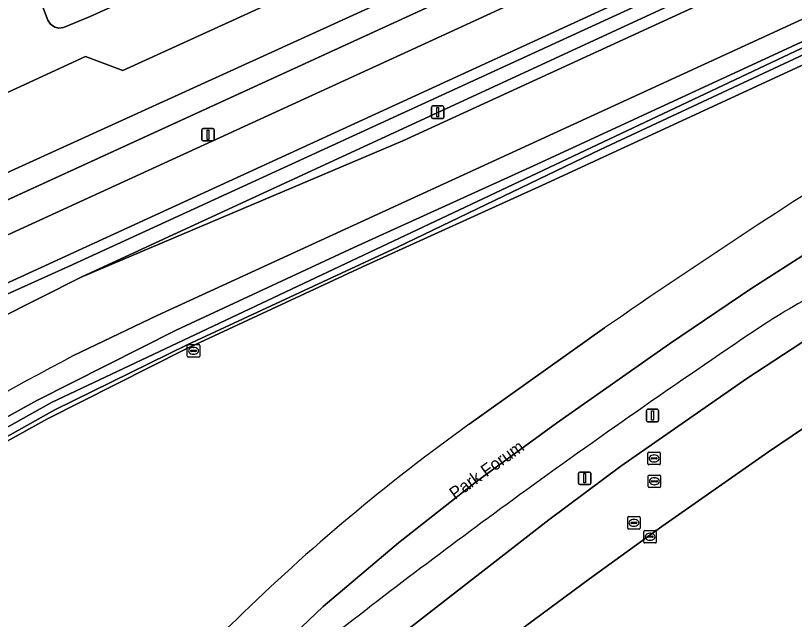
# Model space of a CAD drawing. Extents: x 154324 to 155744, y 382937 to 384188.
# Drawn here: x 155121.6 to 155184.3, y 383931.3 to 383979.9 of the extents above; entities that cross this region are included whole.
import ezdxf

# ---------------------------------------------------------------- set-up
doc = ezdxf.new("R2010")
doc.units = 0
for name, color, linetype in [('IMGEO_Berm_groen', 7, 'Continuous'), ('IMGEO_Brandkraan', 7, 'Continuous'), ('IMGEO_Fietspad_gesloten', 7, 'Continuous'), ('IMGEO_Groenvoorziening', 7, 'Continuous'), ('IMGEO_Hek', 7, 'Continuous'), ('IMGEO_Kolk', 7, 'Continuous'), ('IMGEO_Lichtmast', 7, 'Continuous'), ('IMGEO_Oever', 7, 'Continuous'), ('IMGEO_Openbare_ruimte_label', 7, 'Continuous'), ('IMGEO_Rijbaan_lokaal_gesloten', 7, 'Continuous'), ('IMGEO_Rijbaan_regionaal_gesloten', 7, 'Continuous'), ('IMGEO_Rioolput', 7, 'Continuous'), ('IMGEO_Waterloop', 7, 'Continuous')]:
    doc.layers.add(name, color=color, linetype=linetype)

msp = doc.modelspace()

# ---------------------------------------------------------------- linework, layer by layer
at = {"layer": 'IMGEO_Berm_groen'}
for points in [[(155216.947, 383966.211), (155208.019, 383961.01), (155197.209, 383954.523), (155186.065, 383947.326), (155182.24, 383944.758), (155173.642, 383938.73), (155167.822, 383934.537), (155162.06, 383930.25), (155159.165, 383927.997), (155156.346, 383925.646), (155153.632, 383923.181), (155151.051, 383920.585), (155148.632, 383917.845), (155138.686, 383905.811), (155138.407, 383905.368)], [(155133.588, 383908.721), (155144.709, 383922.37), (155147.219, 383925.163), (155149.95, 383927.749), (155152.834, 383930.186), (155164.546, 383939.275), (155170.363, 383943.609), (155180.51, 383950.671), (155194.401, 383959.769)]]:
    msp.add_lwpolyline(points, dxfattribs=at)
for centre, radius, start, end in [((155226.572, 383884.581), 83.419, 118.05219, 122.35264), ((155550.304, 383405.836), 661.313, 123.850715, 125.881835), ((155500.921, 383476.271), 575.303, 126.008507, 127.98532)]:
    msp.add_arc(centre, radius, start, end, dxfattribs=at)
at = {"layer": 'IMGEO_Brandkraan'}
for p, q in [((155135.434, 383952.47), (155135.434, 383953.322)), ((155135.509, 383953.396), (155136.361, 383953.396)), ((155135.693, 383952.89), (155135.693, 383952.902)), ((155136.131, 383952.853), (155135.733, 383952.853)), ((155135.736, 383952.939), (155136.134, 383952.939)), ((155135.922, 383953.176), (155135.947, 383953.176)), ((155136.177, 383952.902), (155136.177, 383952.89)), ((155136.435, 383953.322), (155136.435, 383952.47)), ((155136.361, 383952.396), (155135.509, 383952.396)), ((155135.945, 383952.616), (155135.92, 383952.616))]:
    msp.add_line(p, q, dxfattribs=at)
for points in [[(155135.434, 383952.47), (155135.434, 383953.322)], [(155135.509, 383953.396), (155136.361, 383953.396)], [(155136.435, 383953.322), (155136.435, 383952.47)], [(155136.361, 383952.396), (155135.509, 383952.396)]]:
    msp.add_lwpolyline(points, dxfattribs=at)
for centre, radius, start, end in [((155135.511, 383953.32), 0.0765, 91.55205, 178.44795), ((155135.511, 383953.32), 0.0765, 91.55205, 178.44795), ((155135.733, 383952.899), 0.0403, 85.87752, 175.75265), ((155135.73, 383952.889), 0.0366, 178.93798, 274.71019), ((155136.134, 383952.896), 0.043, 264.86636, 352.45326), ((155136.138, 383952.901), 0.0386, 1.73085, 96.63898), ((155136.359, 383953.32), 0.0765, 1.55205, 88.44795), ((155136.359, 383953.32), 0.0765, 1.55205, 88.44795), ((155135.511, 383952.472), 0.0765, 181.55205, 268.44795), ((155135.511, 383952.472), 0.0765, 181.55205, 268.44795), ((155136.359, 383952.472), 0.0765, 271.55205, 358.44795), ((155136.359, 383952.472), 0.0765, 271.55205, 358.44795)]:
    msp.add_arc(centre, radius, start, end, dxfattribs=at)
for centre, major_axis, ratio, start_param, end_param in [((155135.921, 383952.896), (-0.387, 0.002), 0.722429, 4.712389, 7.853982), ((155135.946, 383952.896), (-0.39, 0.002), 0.717154, 1.570796, 4.712389)]:
    msp.add_ellipse(centre, major_axis=major_axis, ratio=ratio, start_param=start_param, end_param=end_param, dxfattribs=at)
at = {"layer": 'IMGEO_Fietspad_gesloten'}
msp.add_lwpolyline([(155389.956, 384081.901), (155387.573, 384084.704), (155322.262, 384054.741), (155153.249, 383977.036), (155080.941, 383943.909), (155082.34, 383940.7), (155107.896, 383952.388)], close=True, dxfattribs=at)
at = {"layer": 'IMGEO_Groenvoorziening'}
for points in [[(155565.781, 384171.091), (155345.515, 384070.104), (155302.819, 384050.582), (155259.756, 384030.849), (155227.42, 384015.974), (155215.147, 384010.329), (155198.929, 384002.897), (155192.608, 384000), (155164.663, 383987.193), (155121.842, 383967.653), (155000, 383911.736), (154979.375, 383902.278), (154932.826, 383880.986), (154892.012, 383862.235), (154851.378, 383843.667), (154815.848, 383827.359)], [(155566.728, 384167.1), (155566.214, 384169.267), (155554.91, 384164.088), (155462.373, 384121.668), (155397.138, 384091.79), (155303.667, 384048.873), (155254.498, 384026.37), (155178.427, 383991.44), (155079.739, 383946.19), (155080.941, 383943.909), (155153.249, 383977.036), (155322.262, 384054.741), (155387.573, 384084.704), (155405.572, 384092.961), (155436.252, 384107.036), (155566.728, 384167.1)], [(155567.788, 384162.639), (155567.566, 384163.575), (155437.664, 384103.785), (155406.753, 384089.606), (155389.956, 384081.901), (155107.896, 383952.388), (155082.34, 383940.7), (155068.842, 383934.526), (155068.64, 383933.902), (155125.852, 383959.693), (155390.548, 384081.204), (155436.679, 384102.381), (155567.788, 384162.639)], [(155567.788, 384162.639), (155436.679, 384102.381), (155390.548, 384081.204), (155125.852, 383959.693), (155068.64, 383933.902), (155067.364, 383929.955), (155065.085, 383926.976), (155061.871, 383923.826), (155058.133, 383919.375)], [(155108.958, 383949.826), (155116.785, 383953.754), (155126.877, 383958.819), (155183.941, 383985.208), (155353.768, 384063.115), (155391.259, 384080.368), (155535.377, 384146.692), (155558.223, 384156.124), (155568.361, 384160.227), (155567.788, 384162.639)], [(155568.539, 384159.477), (155568.361, 384160.227), (155558.223, 384156.124), (155535.377, 384146.692), (155391.259, 384080.368), (155353.768, 384063.115), (155183.941, 383985.208), (155126.877, 383958.819), (155152.797, 383969.816), (155391.893, 384079.622), (155407.71, 384086.886), (155495.767, 384127.327), (155520.89, 384138.727), (155531.3, 384143.578), (155545.606, 384149.916)], [(155506.325, 384124.218), (155471.113, 384108.34), (155409.357, 384082.203), (155402.084, 384079.125), (155394.955, 384076.021), (155392.931, 384075.139), (155245.217, 384007.292), (155133.002, 383955.75), (155126.218, 383952.481)], [(154814.358, 383830.633), (154839.69, 383842.281), (154840.841, 383845.49), (154854.169, 383851.557), (154857.346, 383850.36), (154890.485, 383865.503), (154931.282, 383884.256), (154977.682, 383905.512), (154995.084, 383913.444), (155000, 383915.7), (155112.016, 383967.104), (155113.343, 383970.224), (155127.23, 383976.597), (155130.239, 383975.48), (155171.748, 383994.444), (155183.878, 384000), (155301.2, 384053.801), (155344.012, 384073.386), (155384.949, 384092.255), (155386.64, 384095.684), (155399.607, 384101.591)], [(154776.622, 383807.22), (154852.28, 383841.892), (154892.942, 383860.556), (154969.705, 383895.742), (154996.514, 383908.03), (154997.481, 383908.474), (154998.532, 383908.955), (155000.165, 383909.704), (155000.747, 383909.971), (155079.739, 383946.19), (155178.427, 383991.44), (155254.498, 384026.37), (155303.667, 384048.873), (155397.138, 384091.79)], [(155118.285, 383946.124), (155123.303, 383948.901), (155134.537, 383954.573), (155148.835, 383961.231), (155163.617, 383967.939), (155213.131, 383990.84), (155225.593, 383996.741), (155232.744, 383999.887), (155240.567, 384003.683), (155245.77, 384006.066), (155281.079, 384022.24), (155335.13, 384047.346), (155342.51, 384050.527)], [(155343.202, 384048.958), (155335.832, 384045.781), (155281.796, 384020.682), (155246.475, 384004.503), (155241.299, 384002.132), (155233.464, 383998.33), (155226.305, 383995.181), (155213.857, 383989.287), (155164.333, 383966.381), (155149.551, 383959.673), (155135.285, 383953.03), (155124.105, 383947.385), (155119.195, 383944.668)], [(155178.116, 384002.627), (155127.607, 383979.817), (155125.469, 383978.945), (155125.085, 383978.898), (155124.774, 383978.967), (155124.415, 383979.203), (155124.193, 383979.534), (155123.293, 383981.954)], [(155158.138, 383946.978), (155169.042, 383954.737)]]:
    msp.add_lwpolyline(points, dxfattribs=at)
for centre, radius, start, end in [((155481.723, 383503.313), 549.138, 121.79595, 124.70856), ((155223.884, 383765.328), 211.104, 117.5579, 126.68007), ((155251.621, 383816.498), 160.512, 125.62005, 134.36056), ((155224.33, 383839.819), 124.799, 132.88817, 148.35514)]:
    msp.add_arc(centre, radius, start, end, dxfattribs=at)
at = {"layer": 'IMGEO_Hek'}
msp.add_lwpolyline([(154996.514, 383908.03), (155178.427, 383991.44)], dxfattribs=at)
at = {"layer": 'IMGEO_Kolk'}
for p, q in [((155172.281, 383938.417), (155173.133, 383938.417)), ((155172.206, 383937.491), (155172.206, 383938.343)), ((155172.465, 383937.911), (155172.465, 383937.923)), ((155172.903, 383937.874), (155172.505, 383937.874)), ((155172.508, 383937.96), (155172.906, 383937.96)), ((155172.694, 383938.197), (155172.719, 383938.197)), ((155172.949, 383937.923), (155172.949, 383937.911)), ((155173.207, 383938.343), (155173.207, 383937.491)), ((155173.133, 383937.417), (155172.281, 383937.417)), ((155172.717, 383937.637), (155172.692, 383937.637))]:
    msp.add_line(p, q, dxfattribs=at)
for points in [[(155172.281, 383938.417), (155173.133, 383938.417)], [(155172.206, 383937.491), (155172.206, 383938.343)], [(155173.207, 383938.343), (155173.207, 383937.491)], [(155173.133, 383937.417), (155172.281, 383937.417)]]:
    msp.add_lwpolyline(points, dxfattribs=at)
for centre, radius, start, end in [((155172.283, 383938.341), 0.0765, 91.55205, 178.44795), ((155172.283, 383938.341), 0.0765, 91.55205, 178.44795), ((155173.131, 383938.341), 0.0765, 1.55205, 88.44795), ((155173.131, 383938.341), 0.0765, 1.55205, 88.44795), ((155172.505, 383937.92), 0.0403, 85.87752, 175.75265), ((155172.502, 383937.91), 0.0366, 178.93798, 274.71019), ((155172.906, 383937.917), 0.043, 264.86636, 352.45326), ((155172.91, 383937.922), 0.0386, 1.73085, 96.63898), ((155172.283, 383937.493), 0.0765, 181.55205, 268.44795), ((155172.283, 383937.493), 0.0765, 181.55205, 268.44795), ((155173.131, 383937.493), 0.0765, 271.55205, 358.44795), ((155173.131, 383937.493), 0.0765, 271.55205, 358.44795)]:
    msp.add_arc(centre, radius, start, end, dxfattribs=at)
for centre, major_axis, ratio, start_param, end_param in [((155172.693, 383937.917), (-0.387, 0.002), 0.722429, 4.712389, 7.853982), ((155172.718, 383937.917), (-0.39, 0.002), 0.717154, 1.570796, 4.712389)]:
    msp.add_ellipse(centre, major_axis=major_axis, ratio=ratio, start_param=start_param, end_param=end_param, dxfattribs=at)
at = {"layer": 'IMGEO_Lichtmast'}
for p, q in [((155155.108, 383971.722), (155155.108, 383972.522)), ((155155.108, 383972.522), (155155.108, 383971.722)), ((155155.208, 383972.622), (155155.998, 383972.622)), ((155155.998, 383972.622), (155155.208, 383972.622)), ((155156.098, 383972.522), (155156.098, 383971.722)), ((155156.098, 383971.722), (155156.098, 383972.522)), ((155155.998, 383971.622), (155155.208, 383971.622)), ((155155.208, 383971.622), (155155.998, 383971.622)), ((155136.609, 383969.907), (155136.609, 383970.707)), ((155136.609, 383970.707), (155136.609, 383969.907)), ((155136.709, 383970.807), (155137.499, 383970.807)), ((155137.499, 383970.807), (155136.709, 383970.807)), ((155137.599, 383970.707), (155137.599, 383969.907)), ((155137.599, 383969.907), (155137.599, 383970.707)), ((155137.499, 383969.807), (155136.709, 383969.807)), ((155136.709, 383969.807), (155137.499, 383969.807)), ((155172.407, 383947.283), (155172.407, 383948.083)), ((155172.407, 383948.083), (155172.407, 383947.283)), ((155172.507, 383948.183), (155173.297, 383948.183)), ((155173.297, 383948.183), (155172.507, 383948.183)), ((155173.397, 383948.083), (155173.397, 383947.283)), ((155173.397, 383947.283), (155173.397, 383948.083)), ((155173.297, 383947.183), (155172.507, 383947.183)), ((155172.507, 383947.183), (155173.297, 383947.183)), ((155166.945, 383942.229), (155166.945, 383943.029)), ((155166.945, 383943.029), (155166.945, 383942.229)), ((155167.045, 383943.129), (155167.835, 383943.129)), ((155167.835, 383943.129), (155167.045, 383943.129)), ((155167.935, 383943.029), (155167.935, 383942.229)), ((155167.935, 383942.229), (155167.935, 383943.029)), ((155167.835, 383942.129), (155167.045, 383942.129)), ((155167.045, 383942.129), (155167.835, 383942.129))]:
    msp.add_line(p, q, dxfattribs=at)
for points in [[(155155.528, 383972.497), (155155.678, 383972.497), (155155.678, 383971.747), (155155.528, 383971.747), (155155.528, 383972.497)], [(155137.029, 383970.682), (155137.179, 383970.682), (155137.179, 383969.932), (155137.029, 383969.932), (155137.029, 383970.682)], [(155172.827, 383948.058), (155172.977, 383948.058), (155172.977, 383947.308), (155172.827, 383947.308), (155172.827, 383948.058)], [(155167.365, 383943.004), (155167.515, 383943.004), (155167.515, 383942.254), (155167.365, 383942.254), (155167.365, 383943.004)]]:
    msp.add_lwpolyline(points, dxfattribs=at)
for centre, start, end in [((155155.208, 383972.522), 90, 180), ((155155.208, 383972.522), 90, 180), ((155155.998, 383972.522), 0, 90), ((155155.998, 383972.522), 360, 90), ((155155.208, 383971.722), 180, 270), ((155155.208, 383971.722), 180, 270), ((155155.998, 383971.722), 270, 0), ((155155.998, 383971.722), 270, 0), ((155136.709, 383970.707), 90, 180), ((155136.709, 383970.707), 90, 180), ((155137.499, 383970.707), 0, 90), ((155137.499, 383970.707), 360, 90), ((155136.709, 383969.907), 180, 270), ((155136.709, 383969.907), 180, 270), ((155137.499, 383969.907), 270, 0), ((155137.499, 383969.907), 270, 0), ((155172.507, 383948.083), 90, 180), ((155172.507, 383948.083), 90, 180), ((155173.297, 383948.083), 0, 90), ((155173.297, 383948.083), 360, 90), ((155172.507, 383947.283), 180, 270), ((155172.507, 383947.283), 180, 270), ((155173.297, 383947.283), 270, 0), ((155173.297, 383947.283), 270, 0), ((155167.045, 383943.029), 90, 180), ((155167.045, 383943.029), 90, 180), ((155167.835, 383943.029), 0, 90), ((155167.835, 383943.029), 360, 90), ((155167.045, 383942.229), 180, 270), ((155167.045, 383942.229), 180, 270), ((155167.835, 383942.229), 270, 0), ((155167.835, 383942.229), 270, 0)]:
    msp.add_arc(centre, 0.1, start, end, dxfattribs=at)
at = {"layer": 'IMGEO_Oever'}
for points in [[(155342.51, 384050.527), (155335.13, 384047.346), (155281.079, 384022.24), (155245.77, 384006.066), (155240.567, 384003.683), (155232.744, 383999.887), (155225.593, 383996.741), (155213.131, 383990.84), (155163.617, 383967.939), (155148.835, 383961.231), (155134.537, 383954.573), (155123.303, 383948.901), (155118.285, 383946.124)], [(155119.195, 383944.668), (155124.105, 383947.385), (155135.285, 383953.03), (155149.551, 383959.673), (155164.333, 383966.381), (155213.857, 383989.287), (155226.305, 383995.181), (155233.464, 383998.33), (155241.299, 384002.132), (155246.475, 384004.503), (155281.796, 384020.682), (155335.832, 384045.781), (155343.202, 384048.958)], [(155123.293, 383981.954), (155124.193, 383979.534), (155124.415, 383979.203), (155124.774, 383978.967), (155125.085, 383978.898), (155125.469, 383978.945), (155127.607, 383979.817), (155178.116, 384002.627)], [(155075.55, 383904.232), (155082.726, 383903.913), (155089.478, 383902.725), (155099.372, 383899.688), (155100.518, 383899.667), (155101.919, 383900.347), (155105.932, 383905.506), (155106.718, 383906.759), (155107.036, 383909.306), (155106.229, 383916.419), (155105.465, 383918.202), (155103.257, 383919.816), (155101.686, 383921.387), (155101.983, 383922.321), (155104.106, 383922.364), (155106.272, 383921.642), (155106.282, 383923.192), (155107.079, 383928.616), (155108.48, 383932.99), (155111.282, 383937.873), (155113.448, 383940.761), (155117.227, 383944.667), (155124.488, 383948.744), (155189.711, 383979.529)], [(155188.427, 383978.33), (155168.724, 383969.115), (155152.376, 383961.238), (155135.412, 383953.383), (155124.764, 383948.149), (155117.535, 383944.126)]]:
    msp.add_lwpolyline(points, dxfattribs=at)
at = {"layer": 'IMGEO_Rijbaan_lokaal_gesloten'}
for points in [[(154815.848, 383827.359), (154851.378, 383843.667), (154892.012, 383862.235), (154932.826, 383880.986), (154979.375, 383902.278), (155000, 383911.736), (155121.842, 383967.653), (155164.663, 383987.193), (155192.608, 384000), (155198.929, 384002.897), (155215.147, 384010.329), (155227.42, 384015.974), (155259.756, 384030.849), (155302.819, 384050.582), (155345.515, 384070.104), (155565.781, 384171.091)], [(155399.607, 384101.591), (155386.64, 384095.684), (155384.949, 384092.255), (155344.012, 384073.386), (155301.2, 384053.801), (155183.878, 384000), (155171.748, 383994.444), (155130.239, 383975.48), (155127.23, 383976.597), (155113.343, 383970.224), (155112.016, 383967.104), (155000, 383915.7), (154995.084, 383913.444), (154977.682, 383905.512), (154931.282, 383884.256), (154890.485, 383865.503), (154857.346, 383850.36), (154854.169, 383851.557), (154840.841, 383845.49), (154839.69, 383842.281), (154814.358, 383830.633)], [(155138.407, 383905.368), (155138.686, 383905.811), (155148.632, 383917.845), (155151.051, 383920.585), (155153.632, 383923.181), (155156.346, 383925.646), (155159.165, 383927.997), (155162.06, 383930.25), (155167.822, 383934.537), (155173.642, 383938.73), (155182.24, 383944.758), (155186.065, 383947.326), (155197.209, 383954.523), (155208.019, 383961.01), (155216.947, 383966.211)], [(155194.401, 383959.769), (155180.51, 383950.671), (155170.363, 383943.609), (155164.546, 383939.275), (155152.834, 383930.186), (155149.95, 383927.749), (155147.219, 383925.163), (155144.709, 383922.37), (155133.588, 383908.721)]]:
    msp.add_lwpolyline(points, dxfattribs=at)
at = {"layer": 'IMGEO_Rijbaan_regionaal_gesloten'}
for points in [[(155126.218, 383952.481), (155133.002, 383955.75), (155245.217, 384007.292), (155392.931, 384075.139), (155394.955, 384076.021), (155391.893, 384079.622), (155152.797, 383969.816), (155126.877, 383958.819), (155116.785, 383953.754)], [(155127.637, 383909.547), (155129.694, 383913.816), (155135.047, 383920.931), (155140.545, 383926.751), (155146.389, 383932.297), (155152.454, 383937.425), (155158.731, 383942.381), (155165.173, 383947.069), (155174.282, 383953.456), (155180.905, 383957.932), (155196.341, 383967.819), (155207.358, 383974.486), (155208.596, 383974.479), (155209.477, 383974.99)], [(155208.596, 383974.479), (155207.358, 383974.486), (155196.341, 383967.819), (155180.905, 383957.932), (155174.282, 383953.456), (155165.173, 383947.069), (155158.731, 383942.381), (155152.454, 383937.425), (155146.389, 383932.297), (155140.545, 383926.751), (155135.047, 383920.931), (155129.694, 383913.816), (155127.637, 383909.547)], [(155169.042, 383954.737), (155158.138, 383946.978)]]:
    msp.add_lwpolyline(points, dxfattribs=at)
for centre, radius, start, end in [((155481.723, 383503.313), 549.138, 121.79595, 124.70856), ((155226.572, 383884.581), 83.419, 118.05219, 122.35264), ((155550.304, 383405.836), 661.313, 123.850715, 125.881835), ((155223.884, 383765.328), 211.104, 117.5579, 126.68007), ((155251.621, 383816.498), 160.512, 125.62005, 134.36056), ((155500.921, 383476.271), 575.303, 126.008507, 127.98532), ((155224.33, 383839.819), 124.799, 132.88817, 148.35514)]:
    msp.add_arc(centre, radius, start, end, dxfattribs=at)
at = {"layer": 'IMGEO_Rioolput'}
for p, q in [((155172.606, 383944.725), (155173.458, 383944.725)), ((155172.531, 383943.799), (155172.531, 383944.651)), ((155172.79, 383944.219), (155172.79, 383944.231)), ((155173.228, 383944.182), (155172.83, 383944.182)), ((155172.833, 383944.268), (155173.231, 383944.268)), ((155173.019, 383944.505), (155173.044, 383944.505)), ((155173.274, 383944.231), (155173.274, 383944.219)), ((155173.532, 383944.651), (155173.532, 383943.799)), ((155173.458, 383943.725), (155172.606, 383943.725)), ((155173.042, 383943.945), (155173.017, 383943.945)), ((155172.556, 383941.96), (155172.556, 383942.812)), ((155172.631, 383942.886), (155173.483, 383942.886)), ((155173.557, 383942.812), (155173.557, 383941.96)), ((155172.815, 383942.38), (155172.815, 383942.392)), ((155173.253, 383942.343), (155172.855, 383942.343)), ((155172.858, 383942.429), (155173.256, 383942.429)), ((155173.044, 383942.666), (155173.069, 383942.666)), ((155173.299, 383942.392), (155173.299, 383942.38)), ((155173.483, 383941.886), (155172.631, 383941.886)), ((155173.067, 383942.106), (155173.042, 383942.106)), ((155170.904, 383938.612), (155170.904, 383939.464)), ((155170.979, 383939.538), (155171.831, 383939.538)), ((155171.163, 383939.032), (155171.163, 383939.044)), ((155171.206, 383939.081), (155171.604, 383939.081)), ((155171.392, 383939.318), (155171.417, 383939.318)), ((155171.647, 383939.044), (155171.647, 383939.032)), ((155171.905, 383939.464), (155171.905, 383938.612)), ((155171.831, 383938.538), (155170.979, 383938.538)), ((155171.601, 383938.995), (155171.203, 383938.995)), ((155171.415, 383938.758), (155171.39, 383938.758))]:
    msp.add_line(p, q, dxfattribs=at)
for points in [[(155172.606, 383944.725), (155173.458, 383944.725)], [(155172.531, 383943.799), (155172.531, 383944.651)], [(155173.532, 383944.651), (155173.532, 383943.799)], [(155173.458, 383943.725), (155172.606, 383943.725)], [(155172.556, 383941.96), (155172.556, 383942.812)], [(155172.631, 383942.886), (155173.483, 383942.886)], [(155173.557, 383942.812), (155173.557, 383941.96)], [(155173.483, 383941.886), (155172.631, 383941.886)], [(155170.904, 383938.612), (155170.904, 383939.464)], [(155170.979, 383939.538), (155171.831, 383939.538)], [(155171.905, 383939.464), (155171.905, 383938.612)], [(155171.831, 383938.538), (155170.979, 383938.538)]]:
    msp.add_lwpolyline(points, dxfattribs=at)
for centre, radius, start, end in [((155172.608, 383944.649), 0.0765, 91.55205, 178.44795), ((155172.608, 383944.649), 0.0765, 91.55205, 178.44795), ((155173.456, 383944.649), 0.0765, 1.55205, 88.44795), ((155173.456, 383944.649), 0.0765, 1.55205, 88.44795), ((155172.83, 383944.228), 0.0403, 85.87752, 175.75265), ((155172.827, 383944.218), 0.0366, 178.93798, 274.71019), ((155173.231, 383944.225), 0.043, 264.86636, 352.45326), ((155173.235, 383944.23), 0.0386, 1.73085, 96.63898), ((155172.608, 383943.801), 0.0765, 181.55205, 268.44795), ((155172.608, 383943.801), 0.0765, 181.55205, 268.44795), ((155173.456, 383943.801), 0.0765, 271.55205, 358.44795), ((155173.456, 383943.801), 0.0765, 271.55205, 358.44795), ((155172.633, 383942.81), 0.0765, 91.55205, 178.44795), ((155172.633, 383942.81), 0.0765, 91.55205, 178.44795), ((155173.481, 383942.81), 0.0765, 1.55205, 88.44795), ((155173.481, 383942.81), 0.0765, 1.55205, 88.44795), ((155172.855, 383942.389), 0.0403, 85.87752, 175.75265), ((155172.852, 383942.379), 0.0366, 178.93798, 274.71019), ((155173.256, 383942.386), 0.043, 264.86636, 352.45326), ((155173.26, 383942.391), 0.0386, 1.73085, 96.63898), ((155172.633, 383941.962), 0.0765, 181.55205, 268.44795), ((155172.633, 383941.962), 0.0765, 181.55205, 268.44795), ((155173.481, 383941.962), 0.0765, 271.55205, 358.44795), ((155173.481, 383941.962), 0.0765, 271.55205, 358.44795), ((155170.981, 383939.462), 0.0765, 91.55205, 178.44795), ((155170.981, 383939.462), 0.0765, 91.55205, 178.44795), ((155171.203, 383939.041), 0.0403, 85.87752, 175.75265), ((155171.2, 383939.031), 0.0366, 178.93798, 274.71019), ((155171.604, 383939.038), 0.043, 264.86636, 352.45326), ((155171.608, 383939.043), 0.0386, 1.73085, 96.63898), ((155171.829, 383939.462), 0.0765, 1.55205, 88.44795), ((155171.829, 383939.462), 0.0765, 1.55205, 88.44795), ((155170.981, 383938.614), 0.0765, 181.55205, 268.44795), ((155170.981, 383938.614), 0.0765, 181.55205, 268.44795), ((155171.829, 383938.614), 0.0765, 271.55205, 358.44795), ((155171.829, 383938.614), 0.0765, 271.55205, 358.44795)]:
    msp.add_arc(centre, radius, start, end, dxfattribs=at)
for centre, major_axis, ratio, start_param, end_param in [((155173.018, 383944.225), (-0.387, 0.002), 0.722429, 4.712389, 7.853982), ((155173.043, 383944.225), (-0.39, 0.002), 0.717154, 1.570796, 4.712389), ((155173.043, 383942.386), (-0.387, 0.002), 0.722429, 4.712389, 7.853982), ((155173.068, 383942.386), (-0.39, 0.002), 0.717154, 1.570796, 4.712389), ((155171.391, 383939.038), (-0.387, 0.002), 0.722429, 4.712389, 7.853982), ((155171.416, 383939.038), (-0.39, 0.002), 0.717154, 1.570796, 4.712389)]:
    msp.add_ellipse(centre, major_axis=major_axis, ratio=ratio, start_param=start_param, end_param=end_param, dxfattribs=at)
at = {"layer": 'IMGEO_Waterloop'}
for points in [[(155189.711, 383979.529), (155124.488, 383948.744), (155117.227, 383944.667), (155113.448, 383940.761), (155111.282, 383937.873), (155108.48, 383932.99), (155107.079, 383928.616), (155106.282, 383923.192), (155106.272, 383921.642), (155104.106, 383922.364), (155101.983, 383922.321), (155101.686, 383921.387), (155103.257, 383919.816), (155105.465, 383918.202), (155106.229, 383916.419), (155107.036, 383909.306), (155106.718, 383906.759), (155105.932, 383905.506), (155101.919, 383900.347), (155100.518, 383899.667), (155099.372, 383899.688), (155089.478, 383902.725), (155082.726, 383903.913), (155075.55, 383904.232)], [(155117.535, 383944.126), (155124.764, 383948.149), (155135.412, 383953.383), (155152.376, 383961.238), (155168.724, 383969.115), (155188.427, 383978.33)]]:
    msp.add_lwpolyline(points, dxfattribs=at)

# ---------------------------------------------------------------- texts
at = {"layer": 'IMGEO_Openbare_ruimte_label'}
msp.add_text('Park Forum', height=1, rotation=35.72413, dxfattribs=at).set_placement((155156.992, 383940.87))

doc.saveas('drawing.dxf')
